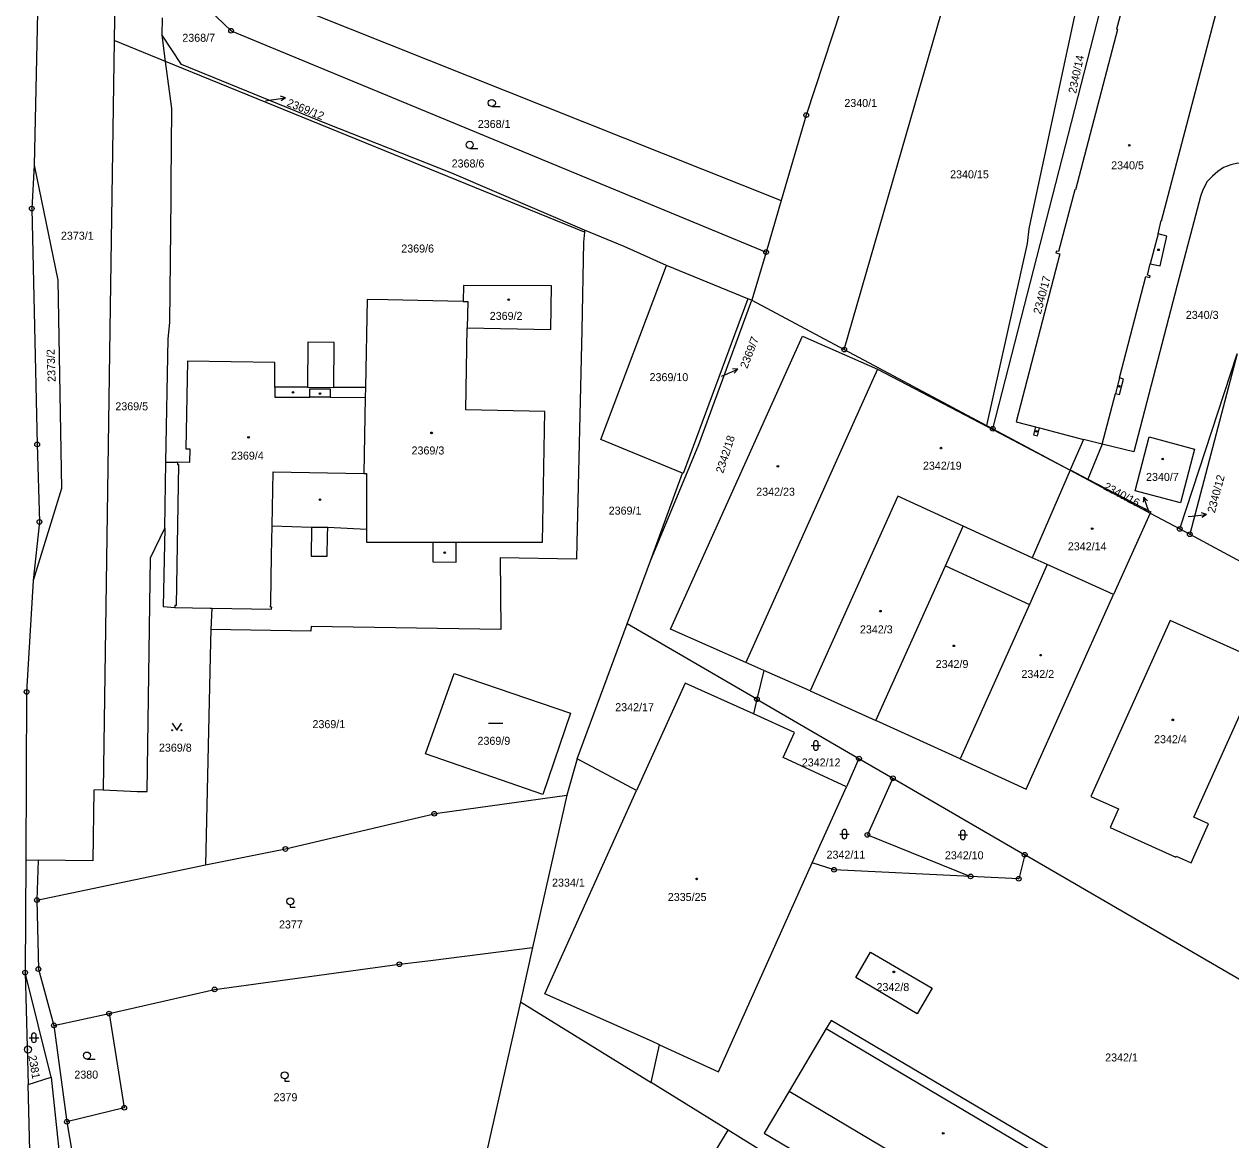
# Model space of a CAD drawing. Extents: x -733394 to -722299, y -1082822 to -1075049.
# Drawn here: x -729380.2 to -729123.9, y -1080113.6 to -1079876.8 of the extents above; entities that cross this region are included whole.
import ezdxf

# ---------------------------------------------------------------- set-up
doc = ezdxf.new("R2010")
doc.units = 0
for name, color, linetype in [('Hranice parcel', 7, 'Continuous'), ('Parcelní čísla', 7, 'Continuous'), ('Pop  PČ popisy', 7, 'Continuous'), ('Vnitřní kresba', 7, 'Continuous'), ('Značky bodu BP', 7, 'Continuous'), ('Značky budov', 7, 'Continuous'), ('Značky kultur', 7, 'Continuous')]:
    doc.layers.add(name, color=color, linetype=linetype)

msp = doc.modelspace()

# ---------------------------------------------------------------- linework, layer by layer
at = {"layer": 'Hranice parcel'}
for p, q in [((-729360.71, -1079857.68), (-729361.04, -1079880.26)), ((-729206.02, -1079945.87), (-729180.91, -1079858.84)), ((-729332.03, -1079869.36), (-729219.43, -1079914.23)), ((-729174.49, -1079962.68), (-729151.07, -1079871.45)), ((-729350.87, -1079879.15), (-729350.8, -1079875.48)), ((-729350.14, -1079884.7), (-729361.04, -1079880.26)), ((-729350.14, -1079884.7), (-729350.87, -1079879.15)), ((-729261.2, -1079920.92), (-729350.14, -1079884.7)), ((-729219.43, -1079914.23), (-729222.64, -1079925.18)), ((-729261.17, -1079920.54), (-729261.2, -1079920.92)), ((-729222.64, -1079925.18), (-729225.64, -1079935.41)), ((-729226.48, -1079935.11), (-729243.75, -1079928.03)), ((-729225.64, -1079935.41), (-729226.48, -1079935.11)), ((-729225.64, -1079935.41), (-729206.02, -1079945.87)), ((-729206.02, -1079945.87), (-729175.85, -1079961.95)), ((-729134.78, -1079983.93), (-729122.63, -1079946.78)), ((-729122.63, -1079946.78), (-729132.65, -1079985.06)), ((-729199, -1079950.06), (-729226.95, -1080012.3)), ((-729175.85, -1079961.95), (-729174.49, -1079962.68)), ((-729174.49, -1079962.68), (-729158.08, -1079971.46)), ((-729151.23, -1079965.96), (-729154.32, -1079973.37)), ((-729247.19, -1079990.7), (-729240.35, -1079972.09)), ((-729158.08, -1079971.46), (-729166.14, -1079990.05)), ((-729158.05, -1079971.41), (-729158.08, -1079971.46)), ((-729158.08, -1079971.46), (-729141.08, -1079980.56)), ((-729158.05, -1079971.41), (-729154.32, -1079973.37)), ((-729141.08, -1079980.56), (-729148.84, -1079997.85)), ((-729141.08, -1079980.56), (-729134.78, -1079983.93)), ((-729166.14, -1079990.05), (-729180.77, -1079983.35)), ((-729134.78, -1079983.93), (-729132.65, -1079985.06)), ((-729132.65, -1079985.06), (-729079.27, -1080013.87)), ((-729162.93, -1079991.52), (-729166.14, -1079990.05)), ((-729252.15, -1080004.07), (-729247.19, -1079990.7)), ((-729148.84, -1079997.85), (-729162.93, -1079991.52)), ((-729340.32, -1080000.76), (-729340.51, -1080005.31)), ((-729262.77, -1080032.73), (-729252.15, -1080004.07)), ((-729224.57, -1080020.08), (-729252.15, -1080004.07)), ((-729223.1, -1080013.98), (-729226.95, -1080012.3)), ((-729223.1, -1080013.98), (-729224.57, -1080020.08)), ((-729213.29, -1080018.27), (-729223.1, -1080013.98)), ((-729213.29, -1080018.27), (-729199.31, -1080024.59)), ((-729224.57, -1080020.08), (-729225.33, -1080023.21)), ((-729224.57, -1080020.08), (-729202.9, -1080032.67)), ((-729181.45, -1080032.73), (-729199.31, -1080024.59)), ((-729262.77, -1080032.73), (-729264.95, -1080040.43)), ((-729250.13, -1080039.49), (-729262.77, -1080032.73)), ((-729202.9, -1080032.67), (-729205.58, -1080038.66)), ((-729202.9, -1080032.67), (-729195.71, -1080036.85)), ((-729212.82, -1080054.82), (-729205.58, -1080038.66)), ((-729195.71, -1080036.85), (-729167.72, -1080053.1)), ((-729264.95, -1080040.43), (-729272.2, -1080072.8)), ((-729379.84, -1080054.19), (-729379.96, -1080078.09)), ((-729379.84, -1080054.19), (-729377.21, -1080054.23)), ((-729377.21, -1080054.23), (-729377.48, -1080062.7)), ((-729099.55, -1080092.69), (-729167.72, -1080053.1)), ((-729377.48, -1080062.7), (-729341.68, -1080055.24)), ((-729272.2, -1080072.8), (-729274.81, -1080084.31)), ((-729379.96, -1080078.09), (-729379.35, -1080101.84)), ((-729374.42, -1080100.33), (-729379.96, -1080078.09)), ((-729274.81, -1080084.31), (-729281.92, -1080115.95)), ((-729274.81, -1080084.31), (-729247.06, -1080101.41)), ((-729373.86, -1080089.3), (-729362.14, -1080086.79)), ((-729373.86, -1080089.3), (-729371.1, -1080109.77)), ((-729247.06, -1080101.41), (-729245.27, -1080093.42)), ((-729379.35, -1080101.84), (-729374.42, -1080100.33)), ((-729230.68, -1080111.53), (-729247.06, -1080101.41)), ((-729371.1, -1080109.77), (-729367.14, -1080133.01)), ((-729242.99, -1080131.58), (-729230.68, -1080111.53)), ((-729125.75, -1080176.43), (-729230.68, -1080111.53))]:
    msp.add_line(p, q, dxfattribs=at)
for points in [[(-729199.41, -1079851.31), (-729214.11, -1079896.1), (-729219.43, -1079914.23)], [(-729377.09, -1079856.58), (-729377.32, -1079874.42), (-729378.08, -1079906.73)], [(-729151.07, -1079871.45), (-729156.11, -1079870.04), (-729166.2, -1079917.17), (-729166.84, -1079920.23), (-729167.2, -1079923.37), (-729175.85, -1079961.95)], [(-729342.41, -1079872.27), (-729336.24, -1079878.19), (-729222.64, -1079925.18)], [(-729151.07, -1079871.45), (-729146.82, -1079872.6), (-729148.19, -1079877.86), (-729148.04, -1079877.9), (-729156.93, -1079911.96), (-729157.09, -1079911.97), (-729160.51, -1079925.08), (-729160.98, -1079924.96), (-729161.08, -1079925.35), (-729160.25, -1079925.56), (-729169.5, -1079961.23), (-729165.43, -1079962.28), (-729165.86, -1079963.93), (-729164.99, -1079964.16), (-729164.56, -1079962.51), (-729155.24, -1079964.92), (-729158.05, -1079971.41)], [(-729151.23, -1079965.96), (-729148.43, -1079955.17), (-729147.56, -1079955.39), (-729146.71, -1079952.12), (-729147.59, -1079951.9), (-729142, -1079930.36), (-729141.15, -1079930.56), (-729141.06, -1079930.2), (-729141.62, -1079930.07), (-729141.05, -1079927.64), (-729138.98, -1079928.12), (-729137.5, -1079921.81), (-729139.39, -1079921.32), (-729138.77, -1079918.5), (-729138.63, -1079918.54), (-729126.08, -1079870.56)], [(-729361.04, -1079880.26), (-729361.88, -1079936.82), (-729363.42, -1080039.33)], [(-729261.17, -1079920.54), (-729289.36, -1079908.41), (-729315.89, -1079897.96), (-729346.77, -1079885.39), (-729350.87, -1079879.15)], [(-729350.3, -1079983.75), (-729350.11, -1079969.75), (-729349.59, -1079943.62), (-729349.26, -1079940.12), (-729348.95, -1079913.77), (-729348.98, -1079910.62), (-729348.82, -1079894.7), (-729350.14, -1079884.7)], [(-729378.08, -1079906.73), (-729378.55, -1079915.93), (-729377.41, -1079966), (-729376.93, -1079982.44), (-729378.27, -1079994.89)], [(-729378.08, -1079906.73), (-729373.02, -1079931.11), (-729372.27, -1079975.34), (-729378.27, -1079994.89)], [(-729111.84, -1079909.06), (-729110.79, -1079908.05), (-729120.37, -1079906.35), (-729122.46, -1079906.31), (-729123.93, -1079906.68), (-729125.48, -1079907.24), (-729126.72, -1079908.09), (-729127.86, -1079909.03), (-729128.95, -1079910.19), (-729129.91, -1079911.98), (-729130.38, -1079913.41), (-729134.9, -1079930.56), (-729144.52, -1079967.54), (-729151.23, -1079965.96)], [(-729261.2, -1079920.92), (-729261.38, -1079923.05), (-729261.75, -1079941.72), (-729262.83, -1079986.89), (-729262.89, -1079990.37), (-729279.11, -1079990.06), (-729278.97, -1080005.29), (-729319.25, -1080004.66), (-729319.27, -1080005.62), (-729340.51, -1080005.31)], [(-729243.75, -1079928.03), (-729252.76, -1079923.99), (-729261.17, -1079920.54)], [(-729240.35, -1079972.09), (-729257.7, -1079964.98), (-729243.75, -1079928.03)], [(-729286.08, -1079941.23), (-729268.37, -1079941.59), (-729268.2, -1079932.37), (-729286.88, -1079932.25), (-729286.97, -1079935.63)], [(-729286.97, -1079935.63), (-729290.21, -1079935.56), (-729302.92, -1079935.3), (-729307.36, -1079935.27), (-729307.72, -1079953.92)], [(-729286.97, -1079935.63), (-729285.97, -1079935.65), (-729286.08, -1079941.23)], [(-729247.19, -1079990.7), (-729236.93, -1079966.04), (-729225.64, -1079935.41)], [(-729226.48, -1079935.11), (-729240.21, -1079972.15), (-729240.35, -1079972.09)], [(-729307.45, -1079983.98), (-729307.45, -1079985.78), (-729307.45, -1079986.78), (-729295.23, -1079986.77), (-729293.37, -1079986.77), (-729293.36, -1079990.94), (-729288.42, -1079990.96), (-729288.42, -1079986.76), (-729270.09, -1079986.75), (-729269.59, -1079959.01), (-729286.41, -1079958.63), (-729286.08, -1079941.23)], [(-729307.72, -1079953.92), (-729314.4, -1079953.9), (-729314.37, -1079944.37), (-729319.91, -1079944.33), (-729319.98, -1079953.88), (-729326.96, -1079953.86), (-729326.94, -1079948.58), (-729345.52, -1079948.31), (-729345.86, -1079966.94), (-729345.01, -1079966.95), (-729345.07, -1079969.85), (-729347.61, -1079969.8), (-729347.62, -1079970.25), (-729347.37, -1079970.25), (-729347.92, -1080000.17), (-729348.17, -1080000.16), (-729348.18, -1080000.61)], [(-729226.95, -1080012.3), (-729242.9, -1080005.23), (-729214.93, -1079943.04), (-729199, -1079950.06)], [(-729199, -1079950.06), (-729175.71, -1079962.18), (-729158.08, -1079971.46)], [(-729307.72, -1079953.92), (-729307.73, -1079956.01), (-729308.07, -1079972.18), (-729307.46, -1079972.19), (-729307.45, -1079983.98)], [(-729134.61, -1079978.38), (-729144.26, -1079975.87), (-729141.29, -1079964.41), (-729131.64, -1079966.98), (-729134.61, -1079978.38)], [(-729154.32, -1079973.37), (-729140.95, -1079980.28), (-729141.08, -1079980.56)], [(-729180.77, -1079983.35), (-729194.66, -1079977), (-729213.29, -1080018.27)], [(-729363.42, -1080039.33), (-729356.16, -1080039.65), (-729354.08, -1080039.64), (-729353.32, -1079990.09), (-729350.3, -1079983.75)], [(-729350.3, -1079983.75), (-729350.66, -1080000.39), (-729348.18, -1080000.61)], [(-729340.32, -1080000.76), (-729327.62, -1080000.99), (-729327.61, -1080000.54), (-729327.86, -1080000.53), (-729327.8, -1079999.79), (-729327.65, -1079989.49), (-729327.53, -1079983.29), (-729319.17, -1079983.53), (-729319.26, -1079989.69), (-729315.85, -1079989.74), (-729315.76, -1079985.35), (-729315.72, -1079983.55), (-729307.45, -1079983.98)], [(-729199.31, -1080024.59), (-729184.56, -1079991.79), (-729180.77, -1079983.35)], [(-729162.93, -1079991.52), (-729166.72, -1079999.95), (-729181.45, -1080032.73)], [(-729378.27, -1079994.89), (-729379.65, -1080018.53), (-729379.84, -1080054.19)], [(-729181.45, -1080032.73), (-729167.39, -1080039.15), (-729148.84, -1079997.85)], [(-729348.18, -1080000.61), (-729340.65, -1080000.75), (-729340.32, -1080000.76)], [(-729147.8, -1080043.35), (-729149.59, -1080047.31), (-729135.6, -1080053.59), (-729135.52, -1080053.41), (-729132.37, -1080054.82), (-729128.65, -1080046.55), (-729131.79, -1080045.13), (-729117.01, -1080012.29), (-729136.85, -1080003.35), (-729153.68, -1080040.7), (-729147.8, -1080043.35)], [(-729340.51, -1080005.31), (-729340.62, -1080007.87), (-729341.68, -1080055.24)], [(-729270.05, -1080040.3), (-729294.92, -1080031.65), (-729288.83, -1080014.59), (-729264.14, -1080023.06), (-729270.05, -1080040.3)], [(-729225.33, -1080023.21), (-729239.83, -1080016.69), (-729250.13, -1080039.49)], [(-729205.58, -1080038.66), (-729218.99, -1080032.48), (-729216.62, -1080027.13), (-729225.33, -1080023.21)], [(-729363.42, -1080039.33), (-729365.39, -1080039.4), (-729365.62, -1080054.4), (-729377.21, -1080054.23)], [(-729195.71, -1080036.85), (-729201.12, -1080048.88), (-729179.2, -1080057.7)], [(-729341.68, -1080055.24), (-729324.68, -1080051.87), (-729296.15, -1080045.12), (-729293.09, -1080044.39), (-729291.9, -1080044.22), (-729264.95, -1080040.43)], [(-729245.27, -1080093.42), (-729246.74, -1080092.75), (-729269.63, -1080082.63), (-729250.13, -1080039.49)], [(-729167.72, -1080053.1), (-729168.98, -1080058.2), (-729179.2, -1080057.7)], [(-729245.27, -1080093.42), (-729232.7, -1080099.17), (-729212.82, -1080054.82)], [(-729179.2, -1080057.7), (-729208.2, -1080056.29), (-729212.82, -1080054.82)], [(-729377.48, -1080062.7), (-729377.13, -1080077.36), (-729373.86, -1080089.3)], [(-729362.14, -1080086.79), (-729339.74, -1080081.69), (-729300.49, -1080076.34), (-729296.83, -1080075.88), (-729293.92, -1080075.51), (-729272.2, -1080072.8)], [(-729190.54, -1080086.84), (-729203.55, -1080079.13), (-729200.49, -1080073.79), (-729187.34, -1080081.38), (-729190.54, -1080086.84)], [(-729362.14, -1080086.79), (-729358.91, -1080106.79), (-729371.1, -1080109.77)], [(-729155.35, -1080122.19), (-729158.8, -1080120.2), (-729157.79, -1080118.42), (-729208.78, -1080088.3), (-729209.85, -1080089.97), (-729217.71, -1080103.27), (-729223.01, -1080112.22), (-729168.71, -1080144.39), (-729166.21, -1080145.87), (-729160.91, -1080136.92)], [(-729374.42, -1080100.33), (-729371.55, -1080127.77), (-729365.2, -1080167.43)], [(-729377.68, -1080171.34), (-729378.49, -1080135.71), (-729379.35, -1080101.84)]]:
    msp.add_lwpolyline(points, dxfattribs=at)
at = {"layer": 'Pop  PČ popisy'}
for p, q in [((-729328.91, -1079893.05), (-729327.65, -1079892.88)), ((-729327.65, -1079892.88), (-729324.68, -1079892.46)), ((-729324.68, -1079892.46), (-729325.74, -1079892.11)), ((-729324.68, -1079892.46), (-729325.6, -1079893.1)), ((-729232.13, -1079951.51), (-729231.42, -1079951.21)), ((-729231.42, -1079951.21), (-729228.66, -1079950.04)), ((-729228.66, -1079950.04), (-729229.78, -1079949.97)), ((-729228.66, -1079950.04), (-729229.38, -1079950.89)), ((-729142.44, -1079977.18), (-729142.58, -1079978.29)), ((-729141.46, -1079980.02), (-729142.44, -1079977.18)), ((-729142.44, -1079977.18), (-729141.64, -1079977.97)), ((-729141.39, -1079980.22), (-729141.46, -1079980.02)), ((-729133.02, -1079981.29), (-729132.12, -1079981.2)), ((-729132.12, -1079981.2), (-729129.14, -1079980.89)), ((-729129.14, -1079980.89), (-729130.18, -1079980.49)), ((-729129.14, -1079980.89), (-729130.08, -1079981.49))]:
    msp.add_line(p, q, dxfattribs=at)
at = {"layer": 'Vnitřní kresba'}
for p, q in [((-729139.39, -1079921.32), (-729141.05, -1079927.64)), ((-729147.59, -1079951.9), (-729148.43, -1079955.17)), ((-729326.96, -1079953.86), (-729326.96, -1079955.95)), ((-729319.98, -1079953.88), (-729314.4, -1079953.9)), ((-729319.49, -1079955.97), (-729319.48, -1079954.18)), ((-729319.48, -1079954.18), (-729315.2, -1079954.19)), ((-729315.2, -1079954.19), (-729315.2, -1079955.99)), ((-729326.96, -1079955.95), (-729319.49, -1079955.97)), ((-729315.2, -1079955.99), (-729319.49, -1079955.97)), ((-729315.2, -1079955.99), (-729307.73, -1079956.01)), ((-729165.43, -1079962.28), (-729164.56, -1079962.51)), ((-729151.23, -1079965.96), (-729155.24, -1079964.92)), ((-729350.11, -1079969.75), (-729347.61, -1079969.8)), ((-729327.53, -1079983.29), (-729327.31, -1079971.81)), ((-729327.31, -1079971.81), (-729308.07, -1079972.18)), ((-729319.17, -1079983.53), (-729315.72, -1079983.55)), ((-729293.37, -1079986.77), (-729288.42, -1079986.76)), ((-729184.56, -1079991.79), (-729166.72, -1079999.95)), ((-729209.85, -1080089.97), (-729158.8, -1080120.2)), ((-729217.71, -1080103.27), (-729163.41, -1080135.44))]:
    msp.add_line(p, q, dxfattribs=at)
at = {"layer": 'Značky bodu BP'}
for centre, radius in [((-729336.24, -1079878.19), 0.5), ((-729336.24, -1079878.19), 0.0303), ((-729214.11, -1079896.1), 0.5), ((-729214.11, -1079896.1), 0.0303), ((-729378.55, -1079915.93), 0.5), ((-729378.55, -1079915.93), 0.0303), ((-729222.64, -1079925.18), 0.5), ((-729222.64, -1079925.18), 0.0303), ((-729206.02, -1079945.87), 0.5), ((-729206.02, -1079945.87), 0.0303), ((-729174.49, -1079962.68), 0.5), ((-729174.49, -1079962.68), 0.0303), ((-729377.41, -1079966), 0.5), ((-729377.41, -1079966), 0.0303), ((-729376.93, -1079982.44), 0.5), ((-729376.93, -1079982.44), 0.0303), ((-729134.78, -1079983.93), 0.5), ((-729134.78, -1079983.93), 0.0303), ((-729132.65, -1079985.06), 0.5), ((-729132.65, -1079985.06), 0.0303), ((-729379.65, -1080018.53), 0.5), ((-729379.65, -1080018.53), 0.0303), ((-729224.57, -1080020.08), 0.5), ((-729224.57, -1080020.08), 0.0303), ((-729202.9, -1080032.67), 0.5), ((-729202.9, -1080032.67), 0.0303), ((-729195.71, -1080036.85), 0.5), ((-729195.71, -1080036.85), 0.0303), ((-729293.09, -1080044.39), 0.5), ((-729293.09, -1080044.39), 0.0303), ((-729201.12, -1080048.88), 0.5), ((-729201.12, -1080048.88), 0.0303), ((-729324.68, -1080051.87), 0.5), ((-729324.68, -1080051.87), 0.0303), ((-729167.72, -1080053.1), 0.5), ((-729167.72, -1080053.1), 0.0303), ((-729208.2, -1080056.29), 0.5), ((-729208.2, -1080056.29), 0.0303), ((-729179.2, -1080057.7), 0.5), ((-729179.2, -1080057.7), 0.0303), ((-729168.98, -1080058.2), 0.5), ((-729168.98, -1080058.2), 0.0303), ((-729377.48, -1080062.7), 0.5), ((-729377.48, -1080062.7), 0.0303), ((-729379.96, -1080078.09), 0.5), ((-729377.13, -1080077.36), 0.5), ((-729377.13, -1080077.36), 0.0303), ((-729300.49, -1080076.34), 0.5), ((-729300.49, -1080076.34), 0.0303), ((-729379.96, -1080078.09), 0.0303), ((-729339.74, -1080081.69), 0.5), ((-729339.74, -1080081.69), 0.0303), ((-729362.14, -1080086.79), 0.5), ((-729362.14, -1080086.79), 0.0303), ((-729373.86, -1080089.3), 0.5), ((-729373.86, -1080089.3), 0.0303), ((-729379.37, -1080094.43), 0.75), ((-729379.37, -1080094.43), 0.03), ((-729358.91, -1080106.79), 0.5), ((-729358.91, -1080106.79), 0.0303), ((-729371.1, -1080109.77), 0.5), ((-729371.1, -1080109.77), 0.0303)]:
    msp.add_circle(centre, radius, dxfattribs=at)
at = {"layer": 'Značky budov'}
for centre in [(-729145.5, -1079902.51), (-729139.3, -1079924.69), (-729277.28, -1079935.29), (-729323.1, -1079954.96), (-729147.61, -1079953.67), (-729317.35, -1079955.2), (-729332.52, -1079964.48), (-729293.67, -1079963.55), (-729165.21, -1079963.21), (-729185.49, -1079966.78), (-729138.41, -1079969.11), (-729220.13, -1079970.66), (-729317.35, -1079977.73), (-729142.14, -1079979.78), (-729153.37, -1079983.89), (-729290.87, -1079988.99), (-729198.35, -1080001.39), (-729182.76, -1080008.75), (-729164.31, -1080010.73), (-729136.26, -1080024.46), (-729237.38, -1080058.21), (-729195.49, -1080077.96), (-729185.01, -1080112.23)]:
    msp.add_circle(centre, 0.175, dxfattribs=at)
at = {"layer": 'Značky kultur'}
for p, q in [((-729280.87, -1079894.28), (-729279.12, -1079894.28)), ((-729285.57, -1079903.16), (-729283.82, -1079903.16)), ((-729281.56, -1080025.17), (-729278.56, -1080025.17)), ((-729213.06, -1080029.9), (-729211.06, -1080029.9)), ((-729212.56, -1080029.4), (-729212.56, -1080030.4)), ((-729211.56, -1080030.4), (-729211.56, -1080029.4)), ((-729207, -1080048.7), (-729205, -1080048.7)), ((-729206.5, -1080048.2), (-729206.5, -1080049.2)), ((-729205.5, -1080049.2), (-729205.5, -1080048.2)), ((-729181.86, -1080048.88), (-729179.86, -1080048.88)), ((-729181.36, -1080048.38), (-729181.36, -1080049.38)), ((-729180.36, -1080049.38), (-729180.36, -1080048.38)), ((-729323.66, -1080063.73), (-729323.66, -1080064.23)), ((-729323.66, -1080064.23), (-729322.66, -1080064.23)), ((-729379.09, -1080091.94), (-729377.09, -1080091.94)), ((-729378.59, -1080091.44), (-729378.59, -1080092.44)), ((-729377.59, -1080092.44), (-729377.59, -1080091.44)), ((-729366.84, -1080096.46), (-729365.09, -1080096.46)), ((-729324.84, -1080100.67), (-729324.84, -1080101.17)), ((-729324.84, -1080101.17), (-729323.84, -1080101.17))]:
    msp.add_line(p, q, dxfattribs=at)
msp.add_lwpolyline([(-729348.77, -1080025.17), (-729347.77, -1080026.67), (-729346.77, -1080025.17)], dxfattribs=at)
for centre, radius in [((-729280.87, -1079893.53), 0.75), ((-729285.57, -1079902.41), 0.75), ((-729348.77, -1080026.67), 0.1), ((-729346.77, -1080026.67), 0.1), ((-729323.66, -1080062.98), 0.75), ((-729366.84, -1080095.71), 0.75), ((-729324.84, -1080099.92), 0.75)]:
    msp.add_circle(centre, radius, dxfattribs=at)
for centre, start, end in [((-729212.06, -1080029.4), 0, 180), ((-729212.06, -1080030.4), 180, 359.9879), ((-729206, -1080048.2), 0, 180), ((-729206, -1080049.2), 180, 359.9879), ((-729180.86, -1080048.38), 0, 180), ((-729180.86, -1080049.38), 180, 359.9879), ((-729378.09, -1080091.44), 0, 180), ((-729378.09, -1080092.44), 180, 359.9879)]:
    msp.add_arc(centre, 0.5, start, end, dxfattribs=at)

# ---------------------------------------------------------------- texts
at = {"layer": 'Parcelní čísla'}
for s, p in [('2368/7', (-729346.59, -1079880.54)), ('2340/1', (-729206.01, -1079894.38)), ('2368/1', (-729283.85, -1079898.83)), ('2368/6', (-729289.4, -1079907.22)), ('2340/5', (-729149.35, -1079907.61)), ('2340/15', (-729183.55, -1079909.52)), ('2373/1', (-729372.36, -1079922.55)), ('2369/6', (-729300.09, -1079925.27)), ('2369/2', (-729281.31, -1079939.57)), ('2340/3', (-729133.5, -1079939.36)), ('2369/10', (-729247.37, -1079952.57)), ('2369/5', (-729360.81, -1079958.76)), ('2369/4', (-729336.25, -1079969.23)), ('2369/3', (-729297.91, -1079968.13)), ('2342/19', (-729189.32, -1079971.36)), ('2340/7', (-729141.95, -1079973.75)), ('2342/23', (-729224.72, -1079976.89)), ('2369/1', (-729256.05, -1079980.9)), ('2342/14', (-729158.56, -1079988.48)), ('2342/3', (-729202.7, -1080006.11)), ('2342/9', (-729186.62, -1080013.46)), ('2342/2', (-729168.41, -1080015.58)), ('2342/17', (-729254.66, -1080022.62)), ('2369/1', (-729318.95, -1080026.22)), ('2369/9', (-729283.91, -1080029.76)), ('2342/4', (-729140.24, -1080029.42)), ('2369/8', (-729351.55, -1080031.21)), ('2342/12', (-729215.05, -1080034.35)), ('2342/11', (-729209.79, -1080053.93)), ('2342/10', (-729184.66, -1080054.06)), ('2334/1', (-729268.08, -1080059.86)), ('2335/25', (-729243.5, -1080062.91)), ('2377', (-729326.06, -1080068.74)), ('2342/8', (-729199.18, -1080082.03)), ('2342/1', (-729150.63, -1080096.97)), ('2380', (-729369.52, -1080100.61)), ('2379', (-729327.21, -1080105.41))]:
    msp.add_text(s, height=1.7, dxfattribs=at).set_placement(p)
for s, rotation, p in [('2340/14', 78, (-729156.81, -1079891.63)), ('2369/12', 338, (-729324.53, -1079894.12)), ('2340/17', 75, (-729164.29, -1079938.46)), ('2369/7', 69, (-729226.64, -1079950.03)), ('2373/2', 92, (-729373.48, -1079952.7)), ('2342/18', 72, (-729231.75, -1079972.25)), ('2340/12', 75, (-729127.34, -1079980.67)), ('2340/16', 332, (-729151.12, -1079975.44)), ('2381', 280, (-729379.29, -1080095.8))]:
    msp.add_text(s, height=1.7, rotation=rotation, dxfattribs=at).set_placement(p)

doc.saveas('drawing.dxf')
